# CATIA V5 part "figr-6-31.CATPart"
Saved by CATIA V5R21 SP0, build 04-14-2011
Part number: Part1
Bounding box of the stored display mesh (mm): x -36 to 36, y -75 to 75, z -15.252 to 15.252
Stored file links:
  D:\CATIA V5R21 E-RESOURCES\CATIA-V5R21\catia-v5r21-prt\c06-catia-v5r21-prt\c06-catia-v5r21-figr-6-31.CATPart
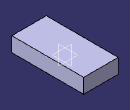
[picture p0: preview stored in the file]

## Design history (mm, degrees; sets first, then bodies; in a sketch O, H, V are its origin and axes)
Body1 (main body)
  Sketch1 on yz-plane, origin (0, 0, 0), H (0, 1, 0), V (0, 0, 1)
    line L1 (-75, 15.2515) -> (75, 15.2515)
    line L2 (75, 15.2515) -> (75, -15.2515)
    line L3 (75, -15.2515) -> (-75, -15.2515)
    line L4 (-75, -15.2515) -> (-75, 15.2515)
    axis line L5 (75, -15.2515) -> (-75, 15.2515)
    length L1 = 150
    horizontal: L1 H, L3 H
    vertical: L2 V, L4 V
    midpoint: O L5
  Pad1: profile Sketch1, direction (1, 0, 0), length 36, mirrored extent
